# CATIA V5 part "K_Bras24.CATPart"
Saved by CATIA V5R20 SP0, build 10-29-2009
Part number: Bras24
Publications: "demilargeur_bras24", "épaisseur_bras24", "Plan yz", "long_pivot_coffre"
Bounding box of the stored display mesh (mm): x -12 to 2, y -143.568 to 5, z -84.984 to 4.998
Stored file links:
  G:\Khaled_CFAO_2011\SIL\SIL_GR2\zthiebault\Khaled\CAD_ThinkMOTION\K_Bras24.CATPart
  F:\Projet Thinkmotion\Catia\FINAL\HabillageFinal.CATProduct
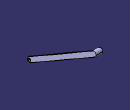
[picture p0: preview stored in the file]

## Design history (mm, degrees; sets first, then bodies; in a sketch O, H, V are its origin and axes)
Parameters
  demilargeur_bras24 = 5 mm
  `épaisseur_bras24` = 2 mm
  long_pivot_coffre = 14 mm
External parameters (linked from other documents)
  External.rayonpivot_bras24 = 3 mm
Set1
  Point1 "Point_base_bras24_haut": linked copy from another document
  Point2 "Point_base_bras24_bas": linked copy from another document
  Line1 "Droite_base_bras24": linked copy from another document
Body1 (main body)
  Sketch1 on yz-plane, origin (0, 0, 0), H (0, 1, 0), V (0, 0, 1)
    line L1 (-2.4995, 4.3304) -> (-141.072, -75.6551)
    arc A1 centre (-138.5724, -79.9855) radius 5 from (-141.072, -75.6551) to (-136.0729, -84.3159) ccw
    point P3 (-138.5724, -79.9855)
    line L2 (-136.0729, -84.3159) -> (2.4995, -4.3304)
    arc A2 centre (0, 0) radius 5 from (2.4995, -4.3304) to (-2.4995, 4.3304) ccw
    point P6 (0, 0)
    reference projected point E1 (0, 0) from Point1
    reference projected point E2 (-138.5724, -79.9855) from Point2
    reference projected line E3 (0, 0) -> (-138.5724, -79.9855) from Line1
    radius A1 = 5 {= demilargeur_bras24}
    tangency: A1 L1, L2 A1, A2 L1, A2 L2
    coincidence: P6 E1, P3 E2
    parallelism: L2 L1, L2 E3
  Pad1: profile Sketch1, direction (1, 0, 0), length 2 {= `épaisseur_bras24`}
  Sketch2 on end face of Pad1, origin (2, 0, 0), H (0, 1, 0), V (0, 0, 1)
    circle A1 centre (0, 0) radius 5
    reference projected arc E1 centre (0, 0) radius 5 from (2.4995, -4.3304) to (-2.4995, 4.3304) ccw from edge [face of Pad1 from Sketch1.A2 | end face of Pad1]
    reference projected arc E2 centre (0, 0) radius 5 from (2.4995, -4.3304) to (-2.4995, 4.3304) ccw from edge [face of Pad1 from Sketch1.A2 | end face of Pad1]
    coincidence: A1 E1
    concentricity: A1 E2
  Pad2: profile Sketch2, direction (-1, 0, 0), length 14 {= long_pivot_coffre}
  Sketch3 on face of Pad2, origin (2, -121.7167, -71.1486), H (0, 1, 0), V (0, 0, 1)
    point P1 (-16.8557, -8.8369)
    reference projected arc E1 centre (-16.8557, -8.8369) radius 5 from (-19.3553, -4.5065) to (-14.3562, -13.1672) ccw from edge [start face of Pad1 | face of Pad1 from Sketch1.A1]
    concentricity: P1 E1
  Hole1: placed by Sketch3, at (2, -138.5724, -79.9855) direction (-1, 0, 0), diameter 6 {= (External.rayonpivot_bras24  )*2}, depth 10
